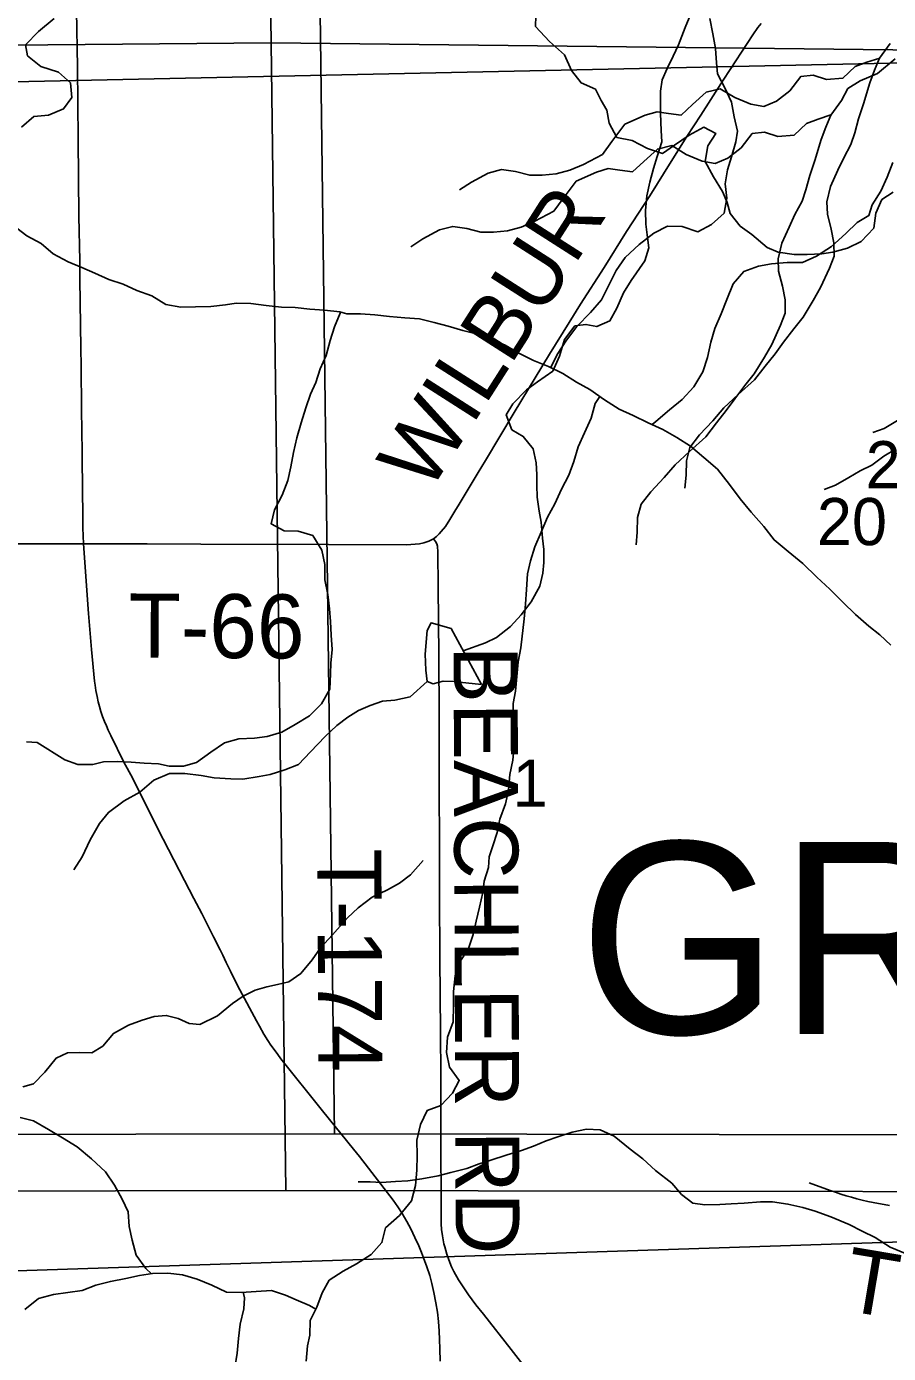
# Model space of a CAD drawing. Extents: x -21.1 to 50.3, y 0 to 22.1.
# Drawn here: x 3.575 to 4.341, y 14.756 to 15.934 of the extents above; entities that cross this region are included whole.
import ezdxf

# ---------------------------------------------------------------- set-up
doc = ezdxf.new("R2010")
doc.units = 0
for name, color, linetype in [('GM_X_County_Road', 7, 'Continuous'), ('GM_X_Minor_Lake', 7, 'Continuous'), ('GM_X_Minor_River', 7, 'Continuous'), ('GM_X_Section', 7, 'Continuous'), ('GM_X_Section_Text', 7, 'Continuous'), ('GM_X_State_Route', 7, 'Continuous'), ('GM_X_Township_Road', 7, 'Continuous'), ('GM_X_Township_Road_Text', 7, 'Continuous'), ('GM_X_Township_Text', 7, 'Continuous')]:
    doc.layers.add(name, color=color, linetype=linetype)

msp = doc.modelspace()

# ---------------------------------------------------------------- linework, layer by layer
at = {"layer": 'GM_X_County_Road'}
msp.add_lwpolyline([(2.6332, 15.477), (2.6882, 15.4768), (2.9046, 15.4768), (3.1601, 15.4764), (3.2587, 15.4761), (3.3033, 15.4759), (3.351, 15.4757), (3.4283, 15.4754), (3.4855, 15.475), (3.6029, 15.4749), (3.6261, 15.4749)], dxfattribs=at)
at = {"layer": 'GM_X_Minor_Lake'}
for points in [[(3.9795, 15.3501), (3.9525, 15.3996), (3.9347, 15.4046), (3.9312, 15.3978), (3.9296, 15.377), (3.9302, 15.3626), (3.9313, 15.3527), (3.9366, 15.3507), (3.9454, 15.353), (3.956, 15.3525), (3.9601, 15.3521)], [(3.9601, 15.3521), (3.9795, 15.3501)]]:
    msp.add_lwpolyline(points, dxfattribs=at)
at = {"layer": 'GM_X_Minor_River'}
for points in [[(3.5709, 15.8449), (3.582, 15.8542), (3.595, 15.8556), (3.6083, 15.8611), (3.6157, 15.8712), (3.6144, 15.8841), (3.6039, 15.8938), (3.588, 15.8986), (3.5764, 15.9083), (3.5746, 15.9178), (3.5859, 15.9298), (3.6001, 15.9413)], [(4.1655, 15.9454), (4.1605, 15.9333), (4.1544, 15.9178), (4.1497, 15.9079), (4.1444, 15.8969), (4.1401, 15.8867), (4.1385, 15.8769), (4.1384, 15.8571), (4.1391, 15.842), (4.1397, 15.8317), (4.1355, 15.8188), (4.1324, 15.8082), (4.1289, 15.7961), (4.1262, 15.784), (4.1253, 15.7707), (4.1256, 15.7586), (4.1267, 15.7491), (4.1281, 15.7377), (4.1246, 15.726), (4.1124, 15.7086), (4.1055, 15.6976), (4.0997, 15.684), (4.0936, 15.673), (4.0818, 15.6678), (4.0723, 15.6697), (4.0624, 15.6683), (4.0532, 15.6562), (4.0489, 15.6414), (4.0428, 15.6282), (4.0291, 15.6188), (4.0195, 15.6116), (4.0073, 15.5992), (4.0015, 15.5894), (4.0064, 15.5761), (4.0166, 15.5703), (4.0253, 15.5593), (4.0282, 15.5467), (4.0285, 15.5365), (4.0285, 15.527), (4.0288, 15.5164), (4.0306, 15.5038), (4.0324, 15.494), (4.0338, 15.4799), (4.0349, 15.4697), (4.0348, 15.4583), (4.034, 15.4488), (4.0313, 15.4374), (4.0236, 15.4234), (4.0148, 15.4117), (4.0052, 15.4015), (3.9927, 15.3918), (3.9831, 15.3869), (3.9633, 15.3799)], [(4.0278, 15.9436), (4.0276, 15.9341), (4.04, 15.921), (4.0531, 15.909), (4.0593, 15.8952), (4.0679, 15.8841), (4.0807, 15.8786), (4.0859, 15.8686), (4.0907, 15.8598), (4.0928, 15.8484), (4.0998, 15.8357), (4.1134, 15.8329), (4.127, 15.8258), (4.1402, 15.8215), (4.151, 15.8289), (4.164, 15.8378), (4.1771, 15.8448), (4.1876, 15.8393), (4.1806, 15.8281), (4.1781, 15.8144)], [(4.1824, 15.9414), (4.1851, 15.9277), (4.1874, 15.9148), (4.1882, 15.9018), (4.189, 15.8923), (4.1955, 15.8798), (4.2016, 15.8669), (4.2039, 15.8539), (4.2069, 15.8414), (4.2054, 15.8319), (4.2016, 15.8186), (4.1979, 15.8068), (4.196, 15.7946), (4.1975, 15.7817), (4.1949, 15.7684), (4.1839, 15.7585), (4.1717, 15.752), (4.1576, 15.7565), (4.1447, 15.7569), (4.1325, 15.7508), (4.1196, 15.7405), (4.107, 15.7291), (4.0991, 15.7177), (4.093, 15.7051), (4.0862, 15.6914), (4.0763, 15.6804), (4.0641, 15.6678), (4.055, 15.6556), (4.0467, 15.6431), (4.0412, 15.6313)], [(4.3425, 15.919), (4.3331, 15.906), (4.3286, 15.8953), (4.3245, 15.8843), (4.3188, 15.8656), (4.3144, 15.8523), (4.311, 15.8398), (4.3076, 15.8295), (4.3012, 15.8177), (4.296, 15.8066), (4.2896, 15.7922), (4.2862, 15.7785), (4.2867, 15.7675), (4.2902, 15.7542), (4.2925, 15.742), (4.2926, 15.7303), (4.2885, 15.7196), (4.2806, 15.7025), (4.2742, 15.691), (4.2651, 15.6762), (4.2568, 15.6659), (4.2477, 15.654), (4.2402, 15.6437), (4.2315, 15.6327), (4.222, 15.6205), (4.2076, 15.6075), (4.1948, 15.5956), (4.1849, 15.5842), (4.1732, 15.5716), (4.1645, 15.5605), (4.1615, 15.5487), (4.1612, 15.5358), (4.1601, 15.5244)], [(4.3332, 15.9062), (4.3217, 15.9025), (4.3114, 15.8987), (4.3005, 15.8883), (4.286, 15.8871), (4.2742, 15.8909), (4.2631, 15.8897), (4.2533, 15.8771), (4.2416, 15.8679), (4.2302, 15.8633), (4.2187, 15.8651), (4.2046, 15.8711), (4.1916, 15.879), (4.1791, 15.8759), (4.167, 15.8648), (4.1568, 15.8556), (4.1457, 15.8571), (4.1354, 15.8585), (4.1248, 15.8555), (4.1069, 15.8474), (4.0952, 15.8321), (4.0869, 15.8207), (4.0702, 15.8118), (4.0581, 15.8065), (4.0459, 15.8033), (4.0333, 15.8021), (4.0223, 15.8021), (4.0097, 15.8054), (3.9972, 15.8073), (3.9854, 15.8041), (3.9706, 15.7961), (3.96, 15.7892)], [(4.347, 15.9056), (4.3311, 15.8926), (4.3159, 15.886), (4.3049, 15.8791), (4.2992, 15.8684), (4.2898, 15.8555), (4.2853, 15.8448), (4.2812, 15.8338), (4.2756, 15.8151), (4.2711, 15.8018), (4.2677, 15.7893), (4.2643, 15.779), (4.2579, 15.7672), (4.2527, 15.7561), (4.2463, 15.7417), (4.2429, 15.728), (4.2434, 15.7169), (4.2469, 15.7037), (4.2492, 15.6915), (4.2493, 15.6797), (4.2452, 15.6691), (4.2373, 15.652), (4.2309, 15.6405), (4.2218, 15.6257), (4.2135, 15.6154), (4.2044, 15.6035), (4.1969, 15.5932), (4.1882, 15.5822), (4.1787, 15.5699), (4.1643, 15.557), (4.1515, 15.5451), (4.1416, 15.5337), (4.1299, 15.5211), (4.1212, 15.51), (4.1182, 15.4982), (4.1179, 15.4853), (4.1168, 15.4739)], [(4.2899, 15.8557), (4.2784, 15.852), (4.2681, 15.8481), (4.2572, 15.8378), (4.2427, 15.8366), (4.2309, 15.8403), (4.2199, 15.8391), (4.21, 15.8265), (4.1983, 15.8174), (4.1869, 15.8127), (4.1755, 15.8146), (4.1613, 15.8206), (4.1484, 15.8285), (4.1358, 15.8254), (4.1237, 15.8143), (4.1135, 15.8051), (4.1024, 15.8066), (4.0921, 15.808), (4.0815, 15.8049), (4.0636, 15.7969), (4.0519, 15.7816), (4.0436, 15.7702), (4.0269, 15.7613), (4.0148, 15.7559), (4.0026, 15.7528), (3.9901, 15.7516), (3.979, 15.7516), (3.9664, 15.7549), (3.9539, 15.7567), (3.9421, 15.7536), (3.9273, 15.7456), (3.9167, 15.7387)], [(4.1311, 15.5807), (4.1343, 15.5835), (4.1464, 15.5938), (4.1578, 15.6029), (4.1681, 15.6143), (4.1761, 15.6277), (4.1802, 15.6402), (4.1832, 15.6539), (4.1867, 15.6661), (4.1923, 15.679), (4.1973, 15.6919), (4.203, 15.7056), (4.2124, 15.7167), (4.2254, 15.7213), (4.2372, 15.7236), (4.2509, 15.7247), (4.2646, 15.7247), (4.2771, 15.7304), (4.2904, 15.7388), (4.303, 15.7503), (4.3132, 15.7602), (4.3235, 15.7663), (4.3265, 15.7758), (4.3341, 15.7879), (4.3398, 15.8005), (4.3447, 15.8134)], [(4.1781, 15.8144), (4.1855, 15.8006), (4.1936, 15.7876), (4.1977, 15.778), (4.2005, 15.7681), (4.2091, 15.757), (4.2196, 15.7496), (4.2331, 15.738), (4.2429, 15.7337), (4.2573, 15.7319), (4.2687, 15.7317), (4.2817, 15.7323), (4.2916, 15.7337), (4.3045, 15.7373), (4.3168, 15.7432), (4.328, 15.7552), (4.3297, 15.7684), (4.3352, 15.7805), (4.3452, 15.7872)], [(3.5629, 15.7581), (3.5758, 15.7482), (3.5884, 15.7414), (3.5991, 15.7323), (3.6124, 15.7254), (3.6246, 15.7201), (3.636, 15.7152), (3.6486, 15.7095), (3.6611, 15.7054), (3.6733, 15.6997), (3.6866, 15.6951), (3.6992, 15.6875), (3.7125, 15.6849), (3.7255, 15.6853), (3.7392, 15.6857), (3.7521, 15.6872), (3.7616, 15.6887), (3.7745, 15.6884), (3.7882, 15.6865), (3.8019, 15.685), (3.8141, 15.6846), (3.8271, 15.6831), (3.84, 15.6824), (3.8537, 15.6809)], [(3.8537, 15.6809), (3.8541, 15.6797), (3.8488, 15.6676), (3.845, 15.6554), (3.8416, 15.6421), (3.8363, 15.6303), (3.8325, 15.6181), (3.8276, 15.6078), (3.8234, 15.5957), (3.8192, 15.5823), (3.8154, 15.569), (3.8124, 15.5561), (3.8102, 15.5432), (3.8075, 15.531), (3.8026, 15.5181), (3.7957, 15.5051), (3.7927, 15.4926), (3.8041, 15.4865), (3.8167, 15.4861), (3.8296, 15.4823), (3.8377, 15.4694), (3.8403, 15.4565), (3.8404, 15.4428), (3.843, 15.4299), (3.8446, 15.4173), (3.8454, 15.4059), (3.8461, 15.3938), (3.8469, 15.3812), (3.8458, 15.369), (3.8454, 15.3595), (3.8447, 15.3458), (3.8375, 15.3329), (3.8268, 15.3222), (3.8139, 15.3146), (3.8021, 15.3078), (3.7892, 15.3039), (3.7778, 15.3024), (3.7641, 15.3016), (3.7512, 15.2982), (3.739, 15.2898), (3.7264, 15.2807), (3.7147, 15.2776), (3.7021, 15.2776), (3.6926, 15.2795), (3.68, 15.2802), (3.6682, 15.281), (3.6561, 15.2817), (3.6439, 15.2813), (3.6344, 15.279), (3.6211, 15.279), (3.6093, 15.2832), (3.5849, 15.2984), (3.5754, 15.2991)], [(3.8537, 15.6809), (3.8598, 15.679), (3.872, 15.679), (3.8849, 15.6783), (3.8978, 15.6767), (3.9115, 15.6756), (3.9245, 15.6745), (3.9374, 15.6715), (3.95, 15.6681), (3.9629, 15.6643), (3.9747, 15.6612), (3.9877, 15.6567), (4.0006, 15.6514), (4.0132, 15.6438), (4.0257, 15.6377), (4.0391, 15.6324), (4.0516, 15.626), (4.0638, 15.6184), (4.0756, 15.6119), (4.0886, 15.6028), (4.1019, 15.5945), (4.1141, 15.5888), (4.1274, 15.5823), (4.1407, 15.5763), (4.1529, 15.5694), (4.1651, 15.5615), (4.1769, 15.5516), (4.1891, 15.5413), (4.1998, 15.5277), (4.2093, 15.5148), (4.2189, 15.503), (4.2303, 15.4904), (4.2394, 15.4783), (4.252, 15.468), (4.265, 15.4574), (4.2772, 15.4452), (4.289, 15.4346), (4.3004, 15.4232), (4.3118, 15.4122), (4.3236, 15.4019), (4.3332, 15.394), (4.3431, 15.3849)], [(4.0846, 15.6056), (4.0806, 15.5994), (4.0768, 15.5865), (4.0711, 15.5735), (4.0654, 15.561), (4.0616, 15.548), (4.0571, 15.5359), (4.0506, 15.5233), (4.0446, 15.5104), (4.0381, 15.4986), (4.0324, 15.4853), (4.0268, 15.4723), (4.023, 15.4598), (4.0203, 15.4483), (4.0196, 15.4343), (4.0185, 15.4213), (4.0173, 15.4084), (4.0143, 15.3826), (4.0121, 15.37), (4.0098, 15.3441), (4.0076, 15.3331), (4.0072, 15.3213), (4.0076, 15.3091), (4.0084, 15.2955), (4.0072, 15.2829), (4.0046, 15.27), (4.0035, 15.2563), (4.0008, 15.2441), (3.9959, 15.2304), (3.9933, 15.2186), (3.9895, 15.2068), (3.9864, 15.1969), (3.9857, 15.1874), (3.9819, 15.1753), (3.9808, 15.1654), (3.9778, 15.1524), (3.9747, 15.1399), (3.9721, 15.1281), (3.9679, 15.1155), (3.9599, 15.1033), (3.9562, 15.0912), (3.9547, 15.0775), (3.9547, 15.0646), (3.9543, 15.0505), (3.9494, 15.0368), (3.9483, 15.0231), (3.951, 15.0102), (3.9597, 14.9984), (3.9537, 14.987), (3.9434, 14.9763), (3.9312, 14.9717), (3.9252, 14.9592), (3.9221, 14.9455), (3.9225, 14.9318), (3.9222, 14.9189), (3.921, 14.9052), (3.9173, 14.8915), (3.9066, 14.8785), (3.8941, 14.8675), (3.8911, 14.8545), (3.8816, 14.8439), (3.8686, 14.8355), (3.8565, 14.829), (3.8443, 14.821), (3.8379, 14.81), (3.8333, 14.7971), (3.8272, 14.7853), (3.8269, 14.7723), (3.825, 14.7628), (3.8239, 14.7491)], [(4.349, 15.5843), (4.3372, 15.5774), (4.327, 15.5736)], [(4.3478, 15.5591), (4.3368, 15.5526), (4.3262, 15.5446), (4.3159, 15.5396), (4.3057, 15.5338), (4.2939, 15.5269), (4.2837, 15.5231)], [(3.9313, 15.3527), (3.916, 15.3391), (3.9024, 15.3362), (3.8917, 15.3351), (3.8807, 15.3314), (3.8704, 15.3269), (3.8609, 15.3209), (3.851, 15.3137), (3.8407, 15.3039), (3.8277, 15.2903), (3.817, 15.279), (3.8048, 15.2742), (3.7919, 15.2701), (3.782, 15.2682), (3.7676, 15.266), (3.7569, 15.2661), (3.7422, 15.267), (3.7304, 15.2693), (3.716, 15.2709), (3.7023, 15.271), (3.6886, 15.265), (3.676, 15.2545), (3.662, 15.2466), (3.6482, 15.2364), (3.6402, 15.2266), (3.6318, 15.2122), (3.6248, 15.1971), (3.6175, 15.1854)], [(3.5721, 14.9928), (3.5816, 14.9953), (3.5917, 15.0058), (3.6017, 15.0182), (3.6117, 15.023), (3.6227, 15.0232), (3.6333, 15.023), (3.6433, 15.029), (3.6526, 15.0402), (3.666, 15.0476), (3.6782, 15.052), (3.6889, 15.0553), (3.6995, 15.0562), (3.7101, 15.0534), (3.7199, 15.0491), (3.7294, 15.0482), (3.7451, 15.0559), (3.7582, 15.0667), (3.7678, 15.0734), (3.7785, 15.0786), (3.7888, 15.0815), (3.7983, 15.0836), (3.8083, 15.0861), (3.819, 15.0935), (3.8291, 15.1056), (3.8365, 15.1161), (3.8473, 15.1277), (3.8604, 15.1427), (3.87, 15.1517), (3.8824, 15.1613), (3.8961, 15.1676), (3.9068, 15.1735), (3.9165, 15.181), (3.9277, 15.1937)], [(3.6865, 14.8268), (3.6814, 14.8315), (3.6727, 14.8432), (3.6692, 14.8566), (3.6666, 14.8687), (3.6658, 14.8817), (3.6604, 14.8931), (3.6536, 14.9056), (3.6456, 14.9174), (3.633, 14.9288), (3.6204, 14.9394), (3.6075, 14.9474), (3.5949, 14.955), (3.5816, 14.9625), (3.5698, 14.9656)], [(4.3175, 14.8647), (4.3061, 14.8704), (4.2898, 14.8774), (4.2758, 14.8824), (4.2648, 14.8855), (4.2516, 14.8886), (4.2379, 14.8906), (4.2273, 14.8907), (4.2129, 14.8896), (4.2011, 14.8889), (4.1912, 14.8882), (4.178, 14.8879), (4.1673, 14.8895), (4.1571, 14.8972), (4.1485, 14.9071), (4.1341, 14.9185), (4.1228, 14.9289), (4.1115, 14.9373), (4.0972, 14.9491), (4.085, 14.9545), (4.0729, 14.9553), (4.06, 14.9524), (4.0474, 14.9483), (4.0368, 14.9449), (4.0258, 14.9401), (4.0151, 14.9363), (4.0022, 14.9323), (3.987, 14.9274), (3.9775, 14.9244), (3.9664, 14.9203), (3.9524, 14.9166), (3.941, 14.9137), (3.9265, 14.9111), (3.914, 14.9093), (3.903, 14.9086), (3.8908, 14.9079), (3.8806, 14.9083), (3.87, 14.9084)], [(4.5467, 14.7513), (4.533, 14.7567), (4.5236, 14.7583), (4.5073, 14.7603), (4.4951, 14.7634), (4.4827, 14.7741), (4.4656, 14.7799), (4.4539, 14.7819), (4.4395, 14.7896), (4.4271, 14.7965), (4.4157, 14.8053), (4.4025, 14.8171), (4.3893, 14.8278), (4.3787, 14.834), (4.3674, 14.8397), (4.356, 14.8447), (4.3424, 14.8505), (4.3292, 14.8589), (4.3175, 14.8647)], [(3.8325, 14.7955), (3.8268, 14.7986), (3.815, 14.8035), (3.8055, 14.8077), (3.793, 14.8118), (3.7793, 14.8111), (3.7659, 14.8103), (3.753, 14.8106), (3.7401, 14.8167), (3.7271, 14.822), (3.7138, 14.8258), (3.7009, 14.8273), (3.6872, 14.8269), (3.6758, 14.8254), (3.6636, 14.8227), (3.6499, 14.82), (3.637, 14.8166), (3.6248, 14.812), (3.6122, 14.8101), (3.5993, 14.8085), (3.586, 14.8047), (3.5738, 14.7952)], [(3.7678, 14.8104), (3.769, 14.8053), (3.7683, 14.7958), (3.7652, 14.7821), (3.7637, 14.7692), (3.7626, 14.7563), (3.7603, 14.7433)]]:
    msp.add_lwpolyline(points, dxfattribs=at)
at = {"layer": 'GM_X_Section'}
for points in [[(3.7784, 16.9399), (3.7926, 15.9197), (2.7351, 15.9102), (2.734, 15.9568), (2.7365, 16.9268)], [(4.8035, 16.9181), (4.8183, 15.9081), (3.7926, 15.9197), (3.7784, 16.9399), (4.3903, 16.9344)], [(4.4944, 16.9022), (4.4951, 15.9048), (3.5076, 15.884), (3.4867, 15.8836), (3.4856, 16.8942)], [(3.8359, 15.9702), (3.8488, 14.9511), (2.7899, 14.9492), (2.7784, 15.9607)], [(3.8359, 15.9702), (4.8616, 15.9586), (4.8737, 14.9494), (3.8488, 14.9511)], [(3.7926, 15.9197), (3.8056, 14.9006), (2.7466, 14.8987), (2.7351, 15.9102)], [(3.7926, 15.9197), (4.8183, 15.9081), (4.8305, 14.8989), (3.8056, 14.9006)], [(4.4951, 15.9048), (4.5163, 14.8604), (3.5576, 14.829), (3.5076, 15.884)]]:
    msp.add_lwpolyline(points, close=True, dxfattribs=at)
at = {"layer": 'GM_X_State_Route'}
msp.add_lwpolyline([(3.9429, 14.7491), (3.9426, 14.7601), (3.9423, 14.7684), (3.942, 14.7757), (3.9412, 14.7844), (3.9403, 14.7927), (3.9389, 14.8011), (3.9372, 14.8103), (3.9355, 14.8181), (3.9335, 14.8252), (3.9309, 14.833), (3.9279, 14.8408), (3.9261, 14.8457), (3.9237, 14.8515), (3.9204, 14.859), (3.9167, 14.8667), (3.9131, 14.8731), (3.9089, 14.8803), (3.9052, 14.8863), (3.9009, 14.8922), (3.871, 14.931), (3.8658, 14.9374), (3.8383, 14.9715), (3.8014, 15.0176), (3.7986, 15.0215), (3.7962, 15.0248), (3.7925, 15.0298), (3.7898, 15.0338), (3.7863, 15.0396), (3.7824, 15.0465), (3.7798, 15.0514), (3.7649, 15.079), (3.7586, 15.0911), (3.7565, 15.0954), (3.7527, 15.1033), (3.7497, 15.1097), (3.7474, 15.1145), (3.7415, 15.1258), (3.731, 15.1467), (3.724, 15.1601), (3.7156, 15.1761), (3.6921, 15.2219), (3.6694, 15.267), (3.6618, 15.2809), (3.6503, 15.3046), (3.6479, 15.3094), (3.6464, 15.3134), (3.6448, 15.3172), (3.643, 15.3216), (3.6415, 15.326), (3.6402, 15.3304), (3.6391, 15.3346), (3.6382, 15.3392), (3.637, 15.3447), (3.6363, 15.3494), (3.6358, 15.353), (3.633, 15.3812), (3.6304, 15.4131), (3.6261, 15.4749), (3.6255, 15.4892), (3.6254, 15.5042), (3.6251, 15.5186), (3.6247, 15.5562), (3.6242, 15.5942), (3.6239, 15.6327), (3.6236, 15.6485), (3.6229, 15.7098), (3.6227, 15.7262), (3.622, 15.7658), (3.6212, 15.8342), (3.6206, 15.8982), (3.6197, 15.9485)], dxfattribs=at)
at = {"layer": 'GM_X_Township_Road'}
for points in [[(3.6261, 15.4749), (3.6825, 15.4748), (3.7303, 15.4746), (3.8437, 15.4742), (3.9129, 15.4741), (3.9244, 15.4749), (3.9284, 15.4757), (3.9328, 15.4772), (3.9369, 15.4794), (3.9395, 15.4814), (3.942, 15.4837), (3.9438, 15.4857), (3.9474, 15.4904), (3.9513, 15.4966), (3.9559, 15.5039), (3.9596, 15.51), (3.9765, 15.5383), (3.9831, 15.5489), (4.0085, 15.5915), (4.0398, 15.6432), (4.0573, 15.6714), (4.0675, 15.6876), (4.0884, 15.7203), (4.1084, 15.7522), (4.129, 15.7839), (4.1481, 15.8142), (4.162, 15.8365), (4.1743, 15.8554), (4.1941, 15.8865), (4.2004, 15.896), (4.2205, 15.9267), (4.2248, 15.9332), (4.2278, 15.9368)], [(3.9434, 14.9767), (3.9434, 14.9826), (3.9433, 15.0055), (3.943, 15.0386), (3.9428, 15.0774), (3.9425, 15.1036), (3.9422, 15.1666), (3.9421, 15.218), (3.942, 15.2476), (3.9419, 15.2778), (3.942, 15.3215), (3.9417, 15.3758), (3.941, 15.4367), (3.9407, 15.4676), (3.9405, 15.4727), (3.9399, 15.475), (3.9387, 15.477), (3.9369, 15.4794)], [(3.9436, 14.8778), (3.9433, 14.9542), (3.9434, 14.9767)], [(4.3419, 14.8875), (4.3371, 14.8883), (4.3322, 14.8891), (4.3273, 14.8901), (4.3225, 14.8911), (4.3177, 14.8922), (4.3128, 14.8934), (4.3081, 14.8947), (4.3033, 14.8961), (4.2986, 14.8975), (4.2939, 14.8991), (4.2892, 14.9007), (4.2704, 14.9074)], [(4.0204, 14.7408), (4.0058, 14.7596), (3.9812, 14.7908), (3.9746, 14.7992), (3.968, 14.8082), (3.9631, 14.8152), (3.9591, 14.8214), (3.9549, 14.8287), (3.953, 14.8328), (3.9513, 14.8367), (3.9488, 14.8442), (3.9468, 14.8508), (3.9461, 14.8535), (3.9454, 14.8569), (3.9448, 14.8606), (3.9441, 14.8662), (3.9438, 14.8712), (3.9436, 14.8778)]]:
    msp.add_lwpolyline(points, dxfattribs=at)

# ---------------------------------------------------------------- texts
at = {"layer": 'GM_X_Section_Text'}
for s, height, p in [('20', 0.04186, (4.3207, 15.5242)), ('20', 0.04186, (4.2774, 15.4737)), ('1', 0.0419, (4.0072, 15.2414))]:
    msp.add_text(s, height=height, rotation=0, dxfattribs=at).set_placement(p)
at = {"layer": 'GM_X_Township_Road_Text'}
for s, height, rotation, p in [('WILBUR', 0.05682, 57.4216, (3.9326, 15.5189)), ('T-66', 0.05682, 359.6465, (3.6659, 15.374)), ('BEACHLER RD', 0.056818, 270.1993, (3.9547, 15.3843)), ('T-174', 0.05682, 270.2797, (3.8337, 15.2042)), ('T', 0.0568, 350.4158, (4.299, 14.7948))]:
    msp.add_text(s, height=height, rotation=rotation, dxfattribs=at).set_placement(p)
at = {"layer": 'GM_X_Township_Text'}
msp.add_text('GRANGER', height=0.17045, rotation=0, dxfattribs=at).set_placement((4.0661, 15.0397))

doc.saveas('drawing.dxf')
